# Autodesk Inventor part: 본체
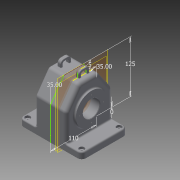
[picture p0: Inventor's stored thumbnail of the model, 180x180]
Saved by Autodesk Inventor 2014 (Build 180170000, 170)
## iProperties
Created: 2016-12
Part Number: 본체
Material: Generic
Document SubType Name: Modeling
Designer: user
Density: 1 g/cm^3
Appearance: Default
Author: user
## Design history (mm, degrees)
sketch "Sketch1"
  geometry: L1 (-75, 55)-(75, 55); L2 (75, 55)-(75, -55); L3 (75, -55)-(-75, -55); L4 (-75, -55)-(-75, 55); L5 (-75, 55)-(75, -55); L6 (75, 55)-(-75, -55); 1 further point
  constraints: 12 end point, 2 midpoint, 2 parallel, 1 horizontal, 1 perpendicular
  dimensions: "d0" = 150 distance of L2.end L3.end; "d1" = 110 distance of L1.end L2.end
extrude "Extrusion1" new body sketch "Sketch1" distance "d2" = 15; taper "d3" = 0 deg
sketch "Sketch2"
  geometry: L1 (-55, 15)-(55, 15) reference; L2 (55, 80)-(55, 0); L3 (55, 0)-(-55, 0); L4 (-55, 0)-(-55, 80); L5 (-55, 80)-(55, 0); L6 (55, 80)-(-55, 0); L7 (-55, 0)-(55, 0) reference; L8 (-55, 80)-(-23.491, 125); L9 (-23.491, 125)-(23.491, 125); L10 (23.491, 125)-(55, 80); 2 further points
  constraints: 16 end point, 2 midpoint, 2 parallel, 1 vertical alignment
  dimensions: "d4" = 110 distance of L2.end L3.end; "d6" = 0 distance between parallel lines of L3 L7; "d7" = 35 deg angle of L4 L8; "d8" = 35 deg angle of L2 L10; "d9" = 125 distance between parallel lines of L9 L3
extrude "Extrusion2" join sketch "Sketch2" stored distance "d10" = 77; taper "d11" = 0 deg
sketch "Sketch3"
  geometry: L1 (-50, 0)-(-50, 80); L2 (50, 0)-(50, 80); L3 (-55, 15)-(-55, 80) reference; L4 (55, 80)-(55, 15) reference; L5 (-20.888, 120)-(-50, 80); L6 (20.888, 120)-(50, 80); L7 (-20.888, 120)-(20.888, 120); L8 (-50, 0)-(50, 0); 1 further point
  constraints: 12 end point, 2 parallel, 1 perpendicular, 1 vertical
  dimensions: "d14" = 80 distance of L1.start L1.end; "d15" = 80 distance of L2.start L2.end; "d16" = 5 distance between parallel lines of L3 L1; "d17" = 5 distance between parallel lines of L4 L2
extrude "Extrusion3" cut sketch "Sketch3" stored distance "d18" = 67; taper "d19" = 0 deg
sketch "Sketch4"
  geometry: L1 (0, 55)-(0, -55) reference; C1 r 37.5 at (-65, 0); 2 further points
  constraints: 1 centre point, 1 horizontal alignment, 1 midpoint
  dimensions: "d20" = 75 diameter of C1; "d21" = 65 distance from line of C1.centre L1
extrude "Extrusion4" join sketch "Sketch4" distance "d22" = 5; taper "d23" = 0 deg
sketch "Sketch5"
  geometry: L1 (0, -55)-(0, 55) reference; C1 r 31 at (65, 0); 2 further points
  constraints: 1 centre point, 1 horizontal alignment, 1 midpoint
  dimensions: "d24" = 62 diameter of C1; "d25" = 65 distance from line of C1.centre L1
extrude "Extrusion5" join sketch "Sketch5" distance "d26" = 10; taper "d27" = 0 deg
sketch "Sketch6"
  geometry: L1 (-43.5, 102.5)-(-43.5, 27.5) reference; L2 (48.5, 34)-(48.5, 96) reference; L3 (-43.5, 65)-(48.5, 65); L4 (-33.5, 109.322)-(-16.178, 92); L5 (-16.178, 92)-(-16.178, 65); L6 (-33.5, 120)-(-33.5, 80) reference; L7 (-33.5, 109.322)-(-33.5, 65); 1 further point
  constraints: 8 end point, 3 point on line, 2 midpoint, 2 perpendicular
  dimensions: "d28" = 45 deg angle of L4 L5; "d29" = 54 diameter of L4.end L3
revolve "Revolution1" sketch "Sketch6" stored, may be unused: angle "d30" = 90 deg
sketch "Sketch7"
  geometry: C1 r 20 at (0, 0); 1 further point
  constraints: 1 centre point
  dimensions: "d31" = 40 diameter of C1
extrude "Extrusion6" cut sketch "Sketch7" stored distance "d32" = 10; taper "d33" = 0 deg
chamfer "Chamfer1" distance "d34" = 1; stored, may be unused: second distance "d35" = 2, angle "d36" = 45 deg
sketch "Sketch8"
  geometry: A1 r 29 centre (0, 0) between (0, 29) and (29, 0); 3 further points
  constraints: 4 point on circle, 1 centre point
  dimensions: "d37" = 58 diameter of A1
hole "Hole1" sketch "Sketch8" at (-29, 0), (0, 29), (29, 0), (0, -29) diameter "d38" = 2.459; stored, may be unused: countersink angle "d42" = 90 deg, drill point angle "d44" = 118 deg; dims "d39" = 6, "d40" = 4, "d41" = 2, "d43" = 8
sketch "Sketch9"
  geometry: A1 r 26 centre (0, 0) between (0, 26) and (26, 0); 3 further points
  constraints: 4 point on circle, 1 centre point
  dimensions: "d45" = 52 diameter of A1
hole "Hole2" sketch "Sketch9" at (26, 0), (0, -26), (-26, 0), (0, 26) diameter "d46" = 2.459; stored, may be unused: countersink angle "d50" = 90 deg, drill point angle "d52" = 118 deg; dims "d47" = 6, "d48" = 4, "d49" = 2, "d51" = 8
fillet "Fillet1" dims "d65" = 10
fillet "Fillet2" dims "d66" = 8
fillet "Fillet3" dims "d67" = 5
fillet "Fillet4" dims "d68" = 4
fillet "Fillet5" dims "d69" = 3
fillet "Fillet6" dims "d70" = 10
fillet "Fillet7" dims "d71" = 3
sketch "Sketch11"
  geometry: A1 r 10 centre (-65, 45) between (-65, 55) and (-75, 45) reference; A2 r 10 centre (65, 45) between (75, 45) and (65, 55) reference; A3 r 10 centre (65, -45) between (65, -55) and (75, -45) reference; A4 r 10 centre (-65, -45) between (-75, -45) and (-65, -55) reference; 5 further points
  constraints: 4 coincident
hole "Hole3" sketch "Sketch11" at (-65, 45), (-65, -45), (65, -45), (65, 45) diameter "d72" = 5; stored, may be unused: countersink angle "d76" = 90 deg, drill point angle "d78" = 0 deg; dims "d73" = 6, "d74" = 12, "d75" = 5, "d77" = 8
sketch "Sketch12"
  geometry: L1 (-34.5, 76.847)-(95.5, 76.847) reference; L2 (69, 0)-(69, 58.847) reference; 2 further points
  constraints: 1 other
  dimensions: "d79" = 45 distance from line of L1 point (30.5, 31.847); "d80" = 38.5 distance from line of point (30.5, 31.847) L2
emboss "Emboss1" sketch "Sketch12" dims "d81" = 0.5, "d82" = 0
fillet "Fillet8" dims "d83" = 3
workplane "Work Plane1"
sketch "Sketch13"
  geometry: L1 (-4.5, 140)-(4.5, 140); L2 (12.5, 132)-(12.5, 125); L3 (-12.5, 125)-(-12.5, 132); L4 (-12.5, 140)-(12.5, 122.977); L5 (12.5, 140)-(-12.5, 122.977); L6 (45, 0)-(-45, 0) reference; L7 (-3.5, 135)-(3.5, 135); L8 (7.5, 131)-(7.5, 125); L9 (-7.5, 125)-(-7.5, 131); L10 (-7.5, 135)-(7.5, 122.913); L11 (7.5, 135)-(-7.5, 122.913); L12 (-12.5, 125)-(12.5, 125); A1 r 4 centre (3.5, 131) between (7.5, 131) and (3.5, 135); A2 r 4 centre (-3.5, 131) between (-3.5, 135) and (-7.5, 131); A3 r 8 centre (4.5, 132) between (12.5, 132) and (4.5, 140); A4 r 8 centre (-4.5, 132) between (-4.5, 140) and (-12.5, 132); 7 further points
  constraints: 22 end point, 10 point on line, 8 point on circle, 8 tangent, 7 midpoint, 4 centre point, 3 perpendicular, 2 equal radius, 2 horizontal, 2 parallel, 2 vertical alignment, 1 coincident
  dimensions: "d86" = 25 distance of L4.end L5.end; "d87" = 140 distance between parallel lines of L6 L1; "d89" = 15 distance of L10.end L11.end; "d90" = 5 distance between parallel lines of L7 L1; "d91" = 4 radius of A1; "d92" = 8 radius of A3
extrude "Extrusion8" join sketch "Sketch13" distance "d93" = 8; taper "d94" = 0 deg
workplane "Work Plane2"
sketch "Sketch14"
  geometry: L1 (-125, 12.5)-(-132, 12.5) reference; L2 (-125, -7.5)-(-125, -12.5); L3 (-125, 12.5)-(-135, 12.5); L4 (-135, 12.5)-(-135, 7.485); L5 (-135, 7.485)-(-125, 7.485); L6 (-125, 7.485)-(-125, 12.5); L7 (-140, 4.5)-(-140, -4.5) reference; L8 (-125, -23.491)-(-125, 23.491) reference; L9 (-125, -7.5)-(-135, -7.5); L10 (-135, -7.5)-(-135, -12.5); L11 (-135, -12.5)-(-125, -12.5); L12 (-125, -12.5)-(-125, -7.5); 2 further points
  constraints: 18 end point, 4 parallel, 2 horizontal, 2 perpendicular
  dimensions: "d95" = 5 distance between parallel lines of L4 L7
mirror "Mirror1"
fillet "Fillet9" dims "d96" = 1
fillet "Fillet10" dims "d97" = 1
fillet "Fillet11" dims "d98" = 1
fillet "Fillet12" dims "d99" = 1
fillet "Fillet13" dims "d100" = 4
body "Solid1"
other parameters: "d84" = 18
